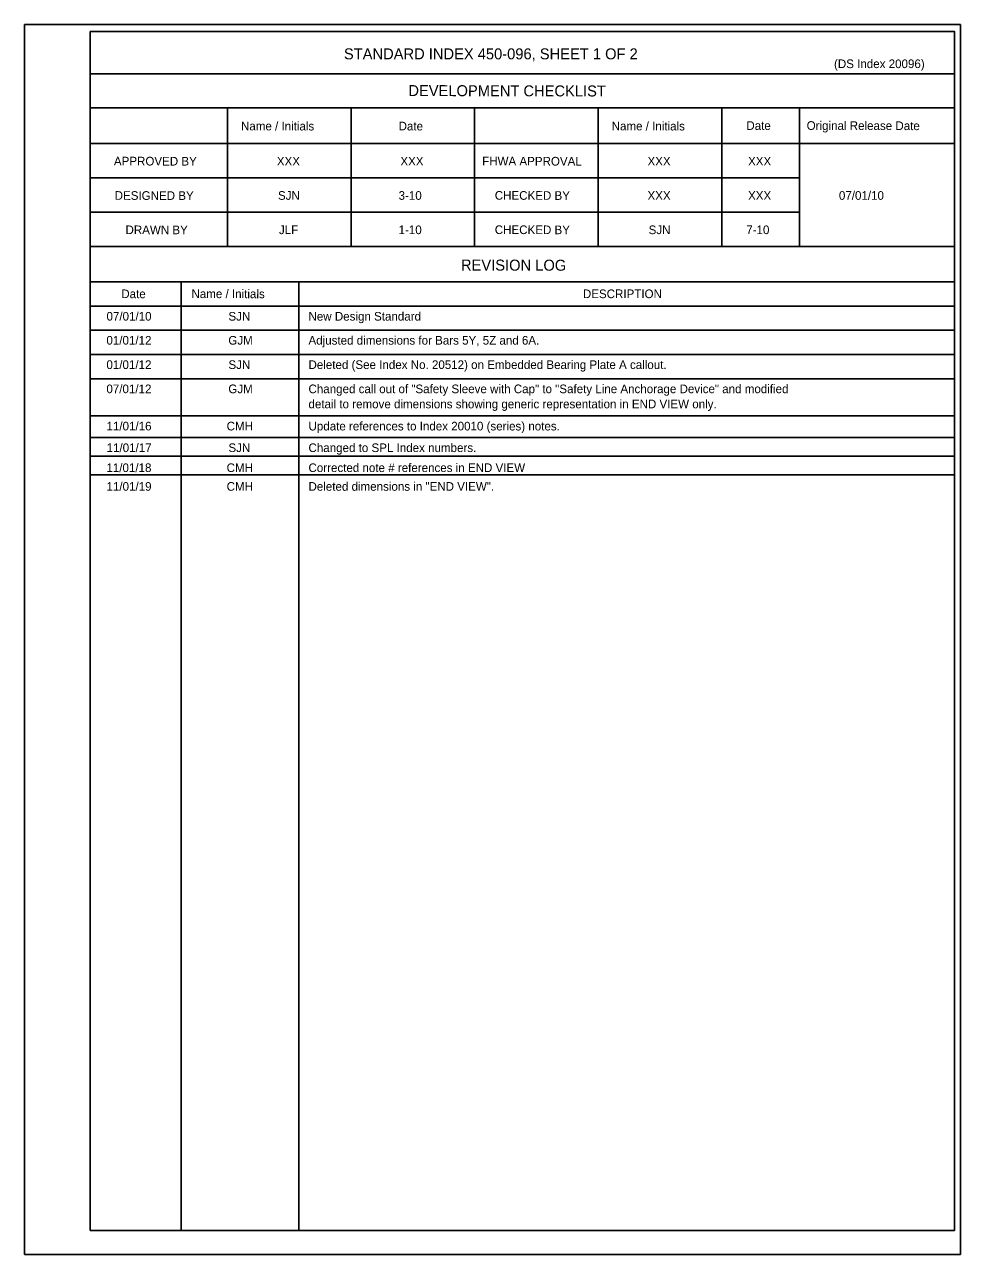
# Model space of a CAD drawing. Extents: x 4.6 to 40.7, y 2.3 to 17.4.
# Drawn here: x 29.79 to 40.7, y 2.25 to 16.59 of the extents above; entities that cross this region are included whole.
import ezdxf

# ---------------------------------------------------------------- set-up
doc = ezdxf.new("R2010")
doc.units = 0
for name, color, linetype in [('Border', 7, 'Continuous'), ('Dimension', 7, 'Continuous'), ('PlotBorder_dp', 7, 'Continuous'), ('TextStructures', 7, 'Continuous')]:
    doc.layers.add(name, color=color, linetype=linetype)

msp = doc.modelspace()

# ---------------------------------------------------------------- linework, layer by layer
at = {"layer": 'Border'}
for p, q in [((40.633, 16.015), (30.559, 16.015)), ((40.633, 15.615), (30.559, 15.615)), ((32.159, 15.615), (32.159, 14.002)), ((33.599, 15.615), (33.599, 14.002)), ((35.039, 15.615), (35.039, 14.002)), ((36.479, 15.615), (36.479, 14.002)), ((37.919, 15.615), (37.919, 14.002)), ((38.827, 15.615), (38.827, 14.002)), ((40.633, 15.202), (30.559, 15.202)), ((38.827, 14.802), (30.559, 14.802)), ((38.827, 14.402), (30.559, 14.402)), ((40.633, 14.002), (30.559, 14.002)), ((40.633, 13.588), (30.559, 13.588)), ((31.62, 13.588), (31.62, 2.534)), ((32.991, 13.588), (32.991, 2.534)), ((40.633, 13.306), (30.559, 13.306))]:
    msp.add_line(p, q, dxfattribs=at)
msp.add_lwpolyline([(30.56, 16.506), (40.633, 16.506), (40.633, 2.534), (30.56, 2.534)], close=True, dxfattribs=at)
at = {"layer": 'Dimension'}
for p, q in [((30.559, 13.024), (40.633, 13.024)), ((30.559, 12.742), (40.633, 12.742)), ((30.559, 12.46), (40.633, 12.46)), ((30.559, 12.026), (40.633, 12.026)), ((30.559, 11.774), (40.633, 11.774)), ((30.559, 11.556), (40.633, 11.556)), ((30.559, 11.339), (40.633, 11.339))]:
    msp.add_line(p, q, dxfattribs=at)
at = {"layer": 'PlotBorder_dp'}
msp.add_line((29.794, 2.254), (29.794, 2.254), dxfattribs=at)
msp.add_lwpolyline([(29.794, 16.587), (40.701, 16.587), (40.701, 2.254), (29.794, 2.254)], close=True, dxfattribs=at)

# ---------------------------------------------------------------- texts
at = {"layer": 'TextStructures'}
for s, height, p in [('STANDARD INDEX 450-096, SHEET 1 OF 2', 0.128, (33.516, 16.182)), ('(DS Index 20096)', 0.1008, (39.228, 16.08)), ('XXX', 0.1008, (32.734, 14.945)), ('XXX', 0.1008, (34.174, 14.945)), ('XXX', 0.1008, (37.054, 14.945)), ('XXX', 0.1008, (38.226, 14.945)), ('SJN', 0.1008, (32.747, 14.545)), ('3-10', 0.1008, (34.153, 14.545)), ('XXX', 0.1008, (37.054, 14.545)), ('XXX', 0.1008, (38.226, 14.545)), ('07/01/10', 0.1008, (39.285, 14.545)), ('JLF', 0.1008, (32.759, 14.145)), ('1-10', 0.1008, (34.153, 14.145)), ('SJN', 0.1008, (37.067, 14.145)), ('7-10', 0.1008, (38.205, 14.145)), ('DESCRIPTION', 0.1008, (36.301, 13.399)), ('07/01/10', 0.1008, (30.749, 13.137)), ('SJN', 0.1008, (32.17, 13.137)), ('New Design Standard', 0.1008, (33.103, 13.137)), ('01/01/12', 0.1008, (30.748, 12.857)), ('GJM', 0.1008, (32.169, 12.857)), ('Adjusted dimensions for Bars 5Y, 5Z and 6A.', 0.1008, (33.103, 12.857)), ('01/01/12', 0.1008, (30.748, 12.573)), ('SJN', 0.1008, (32.17, 12.573)), ('Deleted (See Index No. 20512) on Embedded Bearing Plate A callout.', 0.1008, (33.103, 12.573)), ('07/01/12', 0.1008, (30.748, 12.291)), ('GJM', 0.1008, (32.169, 12.291)), ('Changed call out of "Safety Sleeve with Cap" to "Safety Line Anchorage Device" and modified', 0.1008, (33.103, 12.291)), ('detail to remove dimensions showing generic representation in END VIEW only.', 0.1008, (33.103, 12.115)), ('11/01/16', 0.1008, (30.749, 11.857)), ('CMH', 0.1008, (32.149, 11.857)), ('Update references to Index 20010 (series) notes.', 0.1008, (33.103, 11.857)), ('11/01/17', 0.1008, (30.75, 11.605)), ('SJN', 0.1008, (32.17, 11.605)), ('Changed to SPL Index numbers.', 0.1008, (33.103, 11.605)), ('11/01/18', 0.1008, (30.748, 11.372)), ('CMH', 0.1008, (32.149, 11.372)), ('Corrected note # references in END VIEW', 0.1008, (33.103, 11.372)), ('11/01/19', 0.1008, (30.749, 11.154)), ('CMH', 0.1008, (32.149, 11.154)), ('Deleted dimensions in "END VIEW".', 0.1008, (33.103, 11.154))]:
    msp.add_text(s, height=height, dxfattribs=at).set_placement(p)
for s, height, p in [('DEVELOPMENT CHECKLIST', 0.128, (34.267, 15.754)), ('Name / Initials', 0.1008, (32.316, 15.355)), ('Date', 0.1008, (34.153, 15.354)), ('Name / Initials', 0.1008, (36.636, 15.355)), ('Date', 0.1008, (38.206, 15.36)), ('Original Release Date', 0.1008, (38.909, 15.36)), ('APPROVED BY', 0.1008, (30.835, 14.946)), ('FHWA APPROVAL', 0.1008, (35.127, 14.946)), ('DESIGNED BY', 0.1008, (30.844, 14.545)), ('CHECKED BY', 0.1008, (35.274, 14.546)), ('DRAWN BY', 0.1008, (30.97, 14.145)), ('CHECKED BY', 0.1008, (35.274, 14.146)), ('REVISION LOG', 0.128, (34.88, 13.721)), ('Date', 0.1008, (30.921, 13.399)), ('Name / Initials', 0.1008, (31.739, 13.4))]:
    msp.add_text(s, height=height, rotation=359.8756, dxfattribs=at).set_placement(p)

doc.saveas('drawing.dxf')
